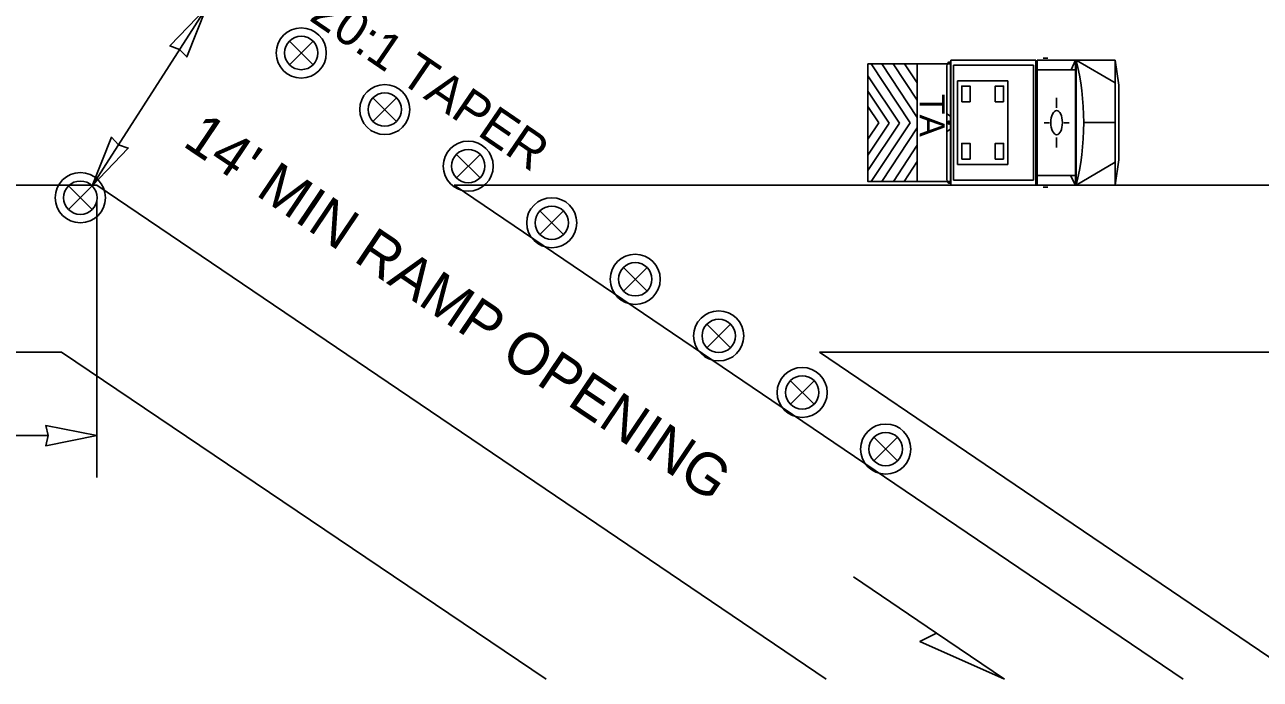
# Model space of a CAD drawing. Extents: x 99999 to 100116, y 99995 to 100013.
# Drawn here: x 100042.573 to 100044.941, y 100006.164 to 100007.419 of the extents above; entities that cross this region are included whole.
import ezdxf

# ---------------------------------------------------------------- set-up
doc = ezdxf.new("R2010")
doc.units = 0
for name, color, linetype in [('RD_MK_LineEdgeYellow', 7, 'Continuous'), ('TR_WZ_TrafficSafetyDrum', 7, 'Continuous'), ('TR_WZ_TransportableAttenuator', 7, 'Continuous'), ('TR_WZ_WorkZoneDetails', 7, 'Continuous'), ('TR_WZ_WorkZoneTextCurrent', 7, 'Continuous')]:
    doc.layers.add(name, color=color, linetype=linetype)

msp = doc.modelspace()

# ---------------------------------------------------------------- linework, layer by layer
at = {"layer": 'RD_MK_LineEdgeYellow'}
for p, q in [((100040.32, 100007.1109), (100042.7119, 100007.1109)), ((100044.1091, 100006.1639), (100042.7119, 100007.1109)), ((100044.0968, 100007.1109), (100047.555, 100007.1109)), ((100044.7935, 100006.1639), (100044.0249, 100006.6849))]:
    msp.add_line(p, q, dxfattribs=at)
at = {"layer": 'TR_WZ_TrafficSafetyDrum'}
for p, q in [((100043.0808, 100007.387), (100043.1261, 100007.3417)), ((100043.1261, 100007.387), (100043.0808, 100007.3417)), ((100043.2408, 100007.2785), (100043.2861, 100007.2333)), ((100043.2861, 100007.2785), (100043.2408, 100007.2333)), ((100043.4008, 100007.1701), (100043.4461, 100007.1248)), ((100043.4461, 100007.1701), (100043.4008, 100007.1248)), ((100042.6574, 100007.1097), (100042.7026, 100007.0644)), ((100042.7026, 100007.1097), (100042.6574, 100007.0644)), ((100043.5608, 100007.0616), (100043.6061, 100007.0164)), ((100043.6061, 100007.0616), (100043.5608, 100007.0164)), ((100043.7208, 100006.9532), (100043.7661, 100006.9079)), ((100043.7661, 100006.9532), (100043.7208, 100006.9079)), ((100043.8808, 100006.8447), (100043.9261, 100006.7995)), ((100043.9261, 100006.8447), (100043.8808, 100006.7995)), ((100044.0408, 100006.7363), (100044.0861, 100006.691)), ((100044.0861, 100006.7363), (100044.0408, 100006.691)), ((100044.2008, 100006.6278), (100044.2461, 100006.5826)), ((100044.2461, 100006.6278), (100044.2008, 100006.5826))]:
    msp.add_line(p, q, dxfattribs=at)
for centre, radius in [((100043.1034, 100007.3644), 0.048), ((100043.1034, 100007.3644), 0.048), ((100043.1034, 100007.3644), 0.032), ((100043.2634, 100007.2559), 0.048), ((100043.2634, 100007.2559), 0.048), ((100043.2634, 100007.2559), 0.032), ((100043.4234, 100007.1475), 0.048), ((100043.4234, 100007.1475), 0.048), ((100043.4234, 100007.1475), 0.032), ((100042.68, 100007.087), 0.048), ((100042.68, 100007.087), 0.048), ((100042.68, 100007.087), 0.032), ((100043.5834, 100007.039), 0.048), ((100043.5834, 100007.039), 0.048), ((100043.5834, 100007.039), 0.032), ((100043.7434, 100006.9306), 0.048), ((100043.7434, 100006.9306), 0.048), ((100043.7434, 100006.9306), 0.032), ((100043.9034, 100006.8221), 0.048), ((100043.9034, 100006.8221), 0.048), ((100043.9034, 100006.8221), 0.032), ((100044.0634, 100006.7137), 0.048), ((100044.0634, 100006.7137), 0.048), ((100044.0634, 100006.7137), 0.032), ((100044.2234, 100006.6052), 0.048), ((100044.2234, 100006.6052), 0.048), ((100044.2234, 100006.6052), 0.032)]:
    msp.add_circle(centre, radius, dxfattribs=at)
at = {"layer": 'TR_WZ_TransportableAttenuator'}
for p, q in [((100044.2157, 100007.3435), (100044.1955, 100007.3435)), ((100044.1955, 100007.3435), (100044.2706, 100007.2307)), ((100044.2706, 100007.2307), (100044.1955, 100007.3435)), ((100044.1955, 100007.3435), (100044.2157, 100007.3435)), ((100044.2839, 100007.2408), (100044.2157, 100007.3435)), ((100044.2157, 100007.3435), (100044.2839, 100007.2408)), ((100044.2593, 100007.3435), (100044.2377, 100007.3435)), ((100044.2377, 100007.3435), (100044.2839, 100007.274)), ((100044.2839, 100007.274), (100044.2377, 100007.3435)), ((100044.2377, 100007.3435), (100044.2593, 100007.3435)), ((100044.2839, 100007.3071), (100044.2593, 100007.3435)), ((100044.2593, 100007.3435), (100044.2839, 100007.3071)), ((100044.3485, 100007.3433), (100044.2839, 100007.3433)), ((100044.2839, 100007.3433), (100044.2839, 100007.118)), ((100044.3444, 100007.347), (100044.3479, 100007.347)), ((100044.3479, 100007.1148), (100044.3479, 100007.347)), ((100044.3485, 100007.3509), (100044.5113, 100007.3509)), ((100044.3485, 100007.1109), (100044.3485, 100007.3509)), ((100044.3485, 100007.1184), (100044.3485, 100007.3433)), ((100044.5113, 100007.1109), (100044.5113, 100007.3509)), ((100044.5135, 100007.1109), (100044.5135, 100007.3509)), ((100044.6631, 100007.3509), (100044.5135, 100007.3509)), ((100044.5339, 100007.3543), (100044.5249, 100007.3543)), ((100044.579, 100007.3323), (100044.5869, 100007.3509)), ((100044.5869, 100007.1109), (100044.5869, 100007.3509)), ((100044.5883, 100007.1109), (100044.5883, 100007.3509)), ((100044.6631, 100007.307), (100044.5883, 100007.3509)), ((100044.6631, 100007.1109), (100044.6631, 100007.3509)), ((100044.6631, 100007.3509), (100044.6704, 100007.3024)), ((100044.2496, 100007.23), (100044.1894, 100007.3205)), ((100044.1894, 100007.3205), (100044.1894, 100007.2911)), ((100044.1894, 100007.2911), (100044.1894, 100007.3205)), ((100044.1894, 100007.3205), (100044.2496, 100007.23)), ((100044.3408, 100007.1221), (100044.3408, 100007.3396)), ((100044.3531, 100007.1205), (100044.3531, 100007.3413)), ((100044.3531, 100007.3413), (100044.5067, 100007.3413)), ((100044.5067, 100007.1205), (100044.5067, 100007.3413)), ((100044.5869, 100007.3323), (100044.5135, 100007.3323)), ((100044.2839, 100007.274), (100044.2839, 100007.3071)), ((100044.2839, 100007.3071), (100044.2839, 100007.274)), ((100044.6704, 100007.1593), (100044.6704, 100007.3024)), ((100044.1894, 100007.2911), (100044.2303, 100007.2297)), ((100044.2303, 100007.2297), (100044.1894, 100007.2911)), ((100044.551, 100007.2784), (100044.551, 100007.2591)), ((100044.2103, 100007.2305), (100044.1894, 100007.2619)), ((100044.1894, 100007.2619), (100044.1894, 100007.1995)), ((100044.1894, 100007.2619), (100044.2103, 100007.2305)), ((100044.1894, 100007.1995), (100044.1894, 100007.2619)), ((100044.3408, 100007.2478), (100044.3479, 100007.2433)), ((100044.1894, 100007.1995), (100044.2103, 100007.2305)), ((100044.2103, 100007.2305), (100044.1894, 100007.1995)), ((100044.1894, 100007.1394), (100044.2496, 100007.23)), ((100044.2496, 100007.23), (100044.1894, 100007.1394)), ((100044.2303, 100007.2297), (100044.1894, 100007.1686)), ((100044.1894, 100007.1686), (100044.2303, 100007.2297)), ((100044.2706, 100007.2307), (100044.1956, 100007.118)), ((100044.1956, 100007.118), (100044.2706, 100007.2307)), ((100044.2839, 100007.2207), (100044.2839, 100007.2408)), ((100044.2839, 100007.2408), (100044.2839, 100007.2207)), ((100044.3427, 100007.2309), (100044.346, 100007.2309)), ((100044.3444, 100007.2275), (100044.3444, 100007.2343)), ((100044.5272, 100007.2307), (100044.5371, 100007.2308)), ((100044.5399, 100007.2313), (100044.5399, 100007.2313)), ((100044.5749, 100007.2307), (100044.5649, 100007.2308)), ((100044.6631, 100007.2309), (100044.603, 100007.2309)), ((100044.2161, 100007.118), (100044.2839, 100007.2207)), ((100044.2839, 100007.2207), (100044.2161, 100007.118)), ((100044.3408, 100007.214), (100044.3479, 100007.2185)), ((100044.551, 100007.1833), (100044.551, 100007.2027)), ((100044.2839, 100007.1875), (100044.2382, 100007.118)), ((100044.2382, 100007.118), (100044.2839, 100007.1875)), ((100044.2839, 100007.1562), (100044.2839, 100007.1875)), ((100044.2839, 100007.1875), (100044.2839, 100007.1562)), ((100044.1894, 100007.1686), (100044.1894, 100007.1394)), ((100044.1894, 100007.1394), (100044.1894, 100007.1686)), ((100044.2586, 100007.118), (100044.2839, 100007.1562)), ((100044.2839, 100007.1562), (100044.2586, 100007.118)), ((100044.6631, 100007.1549), (100044.5883, 100007.1109)), ((100044.6631, 100007.1109), (100044.6704, 100007.1593)), ((100044.5869, 100007.1295), (100044.5135, 100007.1295)), ((100044.5869, 100007.1109), (100044.5774, 100007.1295)), ((100044.1956, 100007.118), (100044.2161, 100007.118)), ((100044.2161, 100007.118), (100044.1956, 100007.118)), ((100044.2382, 100007.118), (100044.2586, 100007.118)), ((100044.2586, 100007.118), (100044.2382, 100007.118)), ((100044.3485, 100007.118), (100044.2839, 100007.118)), ((100044.3444, 100007.1148), (100044.3479, 100007.1148)), ((100044.3485, 100007.1109), (100044.5113, 100007.1109)), ((100044.3531, 100007.1205), (100044.5067, 100007.1205)), ((100044.6631, 100007.1109), (100044.5135, 100007.1109)), ((100044.5339, 100007.1075), (100044.5249, 100007.1075))]:
    msp.add_line(p, q, dxfattribs=at)
for points in [[(100044.2839, 100007.3435), (100044.1894, 100007.3435), (100044.1894, 100007.118), (100044.2839, 100007.118)], [(100044.3611, 100007.1509), (100044.4573, 100007.1509), (100044.4573, 100007.3109), (100044.3611, 100007.3109)], [(100044.3691, 100007.2709), (100044.3852, 100007.2709), (100044.3852, 100007.3009), (100044.3691, 100007.3009)], [(100044.4493, 100007.2709), (100044.4333, 100007.2709), (100044.4333, 100007.3009), (100044.4493, 100007.3009)], [(100044.3691, 100007.1609), (100044.3852, 100007.1609), (100044.3852, 100007.1909), (100044.3691, 100007.1909)], [(100044.4493, 100007.1609), (100044.4333, 100007.1609), (100044.4333, 100007.1909), (100044.4493, 100007.1909)]]:
    msp.add_lwpolyline(points, close=True, dxfattribs=at)
msp.add_lwpolyline([(100044.2839, 100007.118), (100044.1894, 100007.118), (100044.1894, 100007.3435), (100044.2839, 100007.3433)], dxfattribs=at)
for centre, major_axis, start_param, end_param in [((100044.3444, 100007.3396), (0, 0.00732), 0, 1.570796), ((100044.4814, 100007.2309), (0, 0.2519), 4.215667, 5.208926), ((100044.3444, 100007.1222), (0, -0.00732), 4.712389, 6.283185)]:
    msp.add_ellipse(centre, major_axis=major_axis, ratio=0.482618, start_param=start_param, end_param=end_param, dxfattribs=at)
for centre, major_axis in [((100044.551, 100007.2309), (0, -0.0231)), ((100044.3444, 100007.2309), (0, -0.00338))]:
    msp.add_ellipse(centre, major_axis=major_axis, ratio=0.482618, dxfattribs=at)
at = {"layer": 'TR_WZ_WorkZoneDetails'}
for p, q in [((100042.9208, 100007.4502), (100042.7026, 100007.1097)), ((100044.0249, 100006.6849), (100043.3963, 100007.1109)), ((100043.3963, 100007.1109), (100044.0968, 100007.1109)), ((100042.7119, 100006.5509), (100042.7119, 100007.0817)), ((100040.32, 100006.7909), (100042.6438, 100006.7909)), ((100042.6438, 100006.7909), (100043.5728, 100006.1639)), ((100045.0213, 100006.1639), (100044.0968, 100006.7909)), ((100044.0968, 100006.7909), (100047.555, 100006.7909)), ((100042.6182, 100006.6309), (100041.7623, 100006.6309)), ((100044.3211, 100006.2521), (100044.1614, 100006.3604))]:
    msp.add_line(p, q, dxfattribs=at)
for points in [[(100042.9208, 100007.4502), (100042.8516, 100007.3778), (100042.8702, 100007.3713), (100042.884, 100007.357)], [(100042.7026, 100007.1097), (100042.7394, 100007.2028), (100042.7532, 100007.1886), (100042.7719, 100007.182)], [(100042.7119, 100006.6309), (100042.6137, 100006.6116), (100042.6182, 100006.6309), (100042.6137, 100006.6502)], [(100044.4513, 100006.1639), (100044.289, 100006.2366), (100044.3211, 100006.2521)]]:
    msp.add_lwpolyline(points, close=True, dxfattribs=at)

# ---------------------------------------------------------------- texts
at = {"layer": 'TR_WZ_TransportableAttenuator'}
msp.add_text('TA', height=0.0481, rotation=270, dxfattribs=at).set_placement((100044.2883, 100007.2858))
at = {"layer": 'TR_WZ_WorkZoneTextCurrent'}
for s, height, rotation, p in [('20:1 TAPER', 0.07, 325.6617, (100043.1164, 100007.4286)), ("14' MIN RAMP OPENING", 0.08, 326.035, (100042.8737, 100007.1877))]:
    msp.add_text(s, height=height, rotation=rotation, dxfattribs=at).set_placement(p)

doc.saveas('drawing.dxf')
